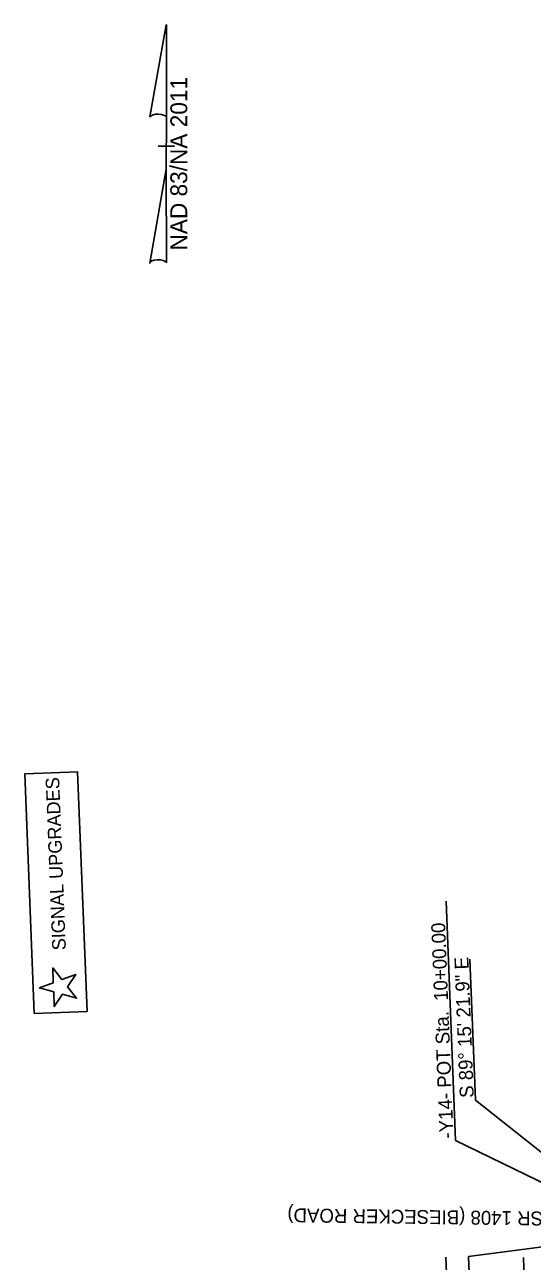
# Model space of a CAD drawing. Extents: x 1627861 to 1629601, y 761281 to 766239.
# Drawn here: x 1627861 to 1628116, y 764815 to 765436 of the extents above; entities that cross this region are included whole.
import ezdxf

# ---------------------------------------------------------------- set-up
doc = ezdxf.new("R2010")
doc.units = 0
for name, color, linetype in [('Cogo Default Point CELL', 7, 'Continuous'), ('Exist Other Culture Sign Leader', 7, 'Continuous'), ('Exist Right of Way Line Leader', 7, 'Continuous'), ('Exist Utilities Power UG Cable SUE LOS B Cogo Elevation', 7, 'Continuous'), ('Exist Utilities Power UG Cable SUE LOS B Cogo Number', 7, 'Continuous'), ('Old_Level_2', 7, 'Continuous'), ('Scratch_Level_0', 7, 'Continuous')]:
    doc.layers.add(name, color=color, linetype=linetype)

msp = doc.modelspace()

# ---------------------------------------------------------------- linework, layer by layer
at = {"layer": 'Exist Right of Way Line Leader'}
for p, q in [((1628077.26, 764876.02), (1628072.53, 764996.09)), ((1628087.22, 764896.19), (1628084.43, 764967.06)), ((1628087.22, 764896.19), (1628158.92, 764839.46)), ((1628150.61, 764840.21), (1628077.26, 764876.02)), ((1628077.02, 764698.58), (1628072.33, 764817.34))]:
    msp.add_line(p, q, dxfattribs=at)
at = {"layer": 'Exist Utilities Power UG Cable SUE LOS B Cogo Elevation'}
msp.add_lwpolyline([(1627875.26, 764950.62), (1627875.55, 764943.22), (1627879.66, 764949.38), (1627886.81, 764947.37), (1627882.21, 764953.2), (1627886.33, 764959.37), (1627879.37, 764956.8), (1627874.78, 764962.62), (1627875.08, 764955.21), (1627868.11, 764952.63), (1627875.26, 764950.62)], dxfattribs=at)
at = {"layer": 'Exist Utilities Power UG Cable SUE LOS B Cogo Number'}
for p, q in [((1627923.64, 765390.11), (1627931.86, 765436.46)), ((1627931.91, 765436.46), (1627931.86, 765436.46)), ((1627931.91, 765436.46), (1627931.86, 765436.46)), ((1627931.91, 765436.46), (1627931.89, 765388.66)), ((1627931.88, 765363.86), (1627931.89, 765390.06)), ((1627931.89, 765388.66), (1627931.89, 765390.01)), ((1627927.88, 765375.46), (1627927.83, 765375.46)), ((1627931.43, 765375.46), (1627927.88, 765375.46)), ((1627927.93, 765375.46), (1627935.93, 765375.46)), ((1627931.88, 765363.86), (1627923.51, 765316.61)), ((1627931.91, 765316.81), (1627931.88, 765363.86))]:
    msp.add_line(p, q, dxfattribs=at)
for centre, start_param, end_param in [((1627927.78, 765389.61), 0.216388, 2.908219), ((1627927.74, 765316.44), 0.201328, 3.141593)]:
    msp.add_ellipse(centre, major_axis=(4.23, -0.03), ratio=0.461098, start_param=start_param, end_param=end_param, dxfattribs=at)
at = {"layer": 'Old_Level_2'}
msp.add_lwpolyline([(1627865.44, 764939.75), (1627860.7, 765060.06), (1627887.3, 765061.11), (1627892.05, 764940.8)], close=True, dxfattribs=at)
at = {"layer": 'Scratch_Level_0'}
for p, q in [((1628241.95, 764838.39), (1628083.84, 764817.64)), ((1628083.84, 764817.64), (1628088.14, 764708.47)), ((1628111.37, 764817.14), (1628115.69, 764707.44))]:
    msp.add_line(p, q, dxfattribs=at)

# ---------------------------------------------------------------- texts
at = {"layer": 'Cogo Default Point CELL'}
msp.add_text('S 89%%d 15\' 21.9" E', height=7, rotation=92.25819, dxfattribs=at).set_placement((1628086.45, 764897.5))
at = {"layer": 'Exist Other Culture Sign Leader'}
for s, height, rotation, p in [('SIGNAL UPGRADES', 6.8072, 92.25819, (1627881.41, 764971.6)), ('-Y14- SR 1408 (BIESECKER ROAD)', 7, 179.25608, (1628146.73, 764839.9))]:
    msp.add_text(s, height=height, rotation=rotation, dxfattribs=at).set_placement(p)
at = {"layer": 'Exist Right of Way Line Leader'}
msp.add_text('-Y14- POT Sta.  10+00.00', height=7, rotation=92.25819, dxfattribs=at).set_placement((1628076.25, 764877.11))
at = {"layer": 'Exist Utilities Power UG Cable SUE LOS B Cogo Number'}
msp.add_text('NAD 83/NA 2011', height=8.5, rotation=89.97566, dxfattribs=at).set_placement((1627942.38, 765323.03))

doc.saveas('drawing.dxf')
